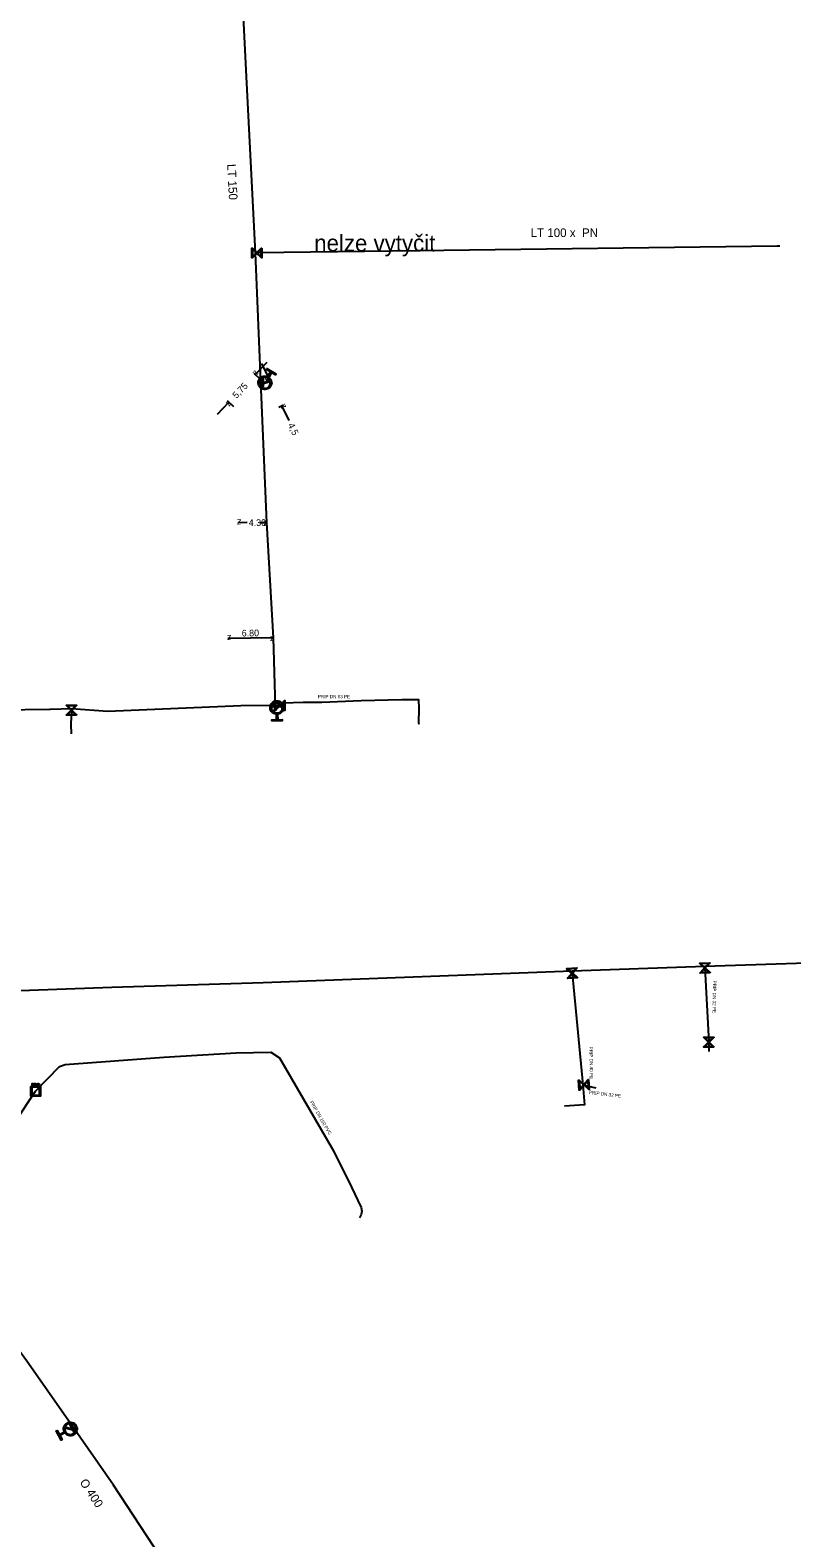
# Model space of a CAD drawing. Extents: x -643544 to -637295, y -1119190 to -1111715.
# Drawn here: x -641541.9 to -641427.5, y -1115022.6 to -1114796 of the extents above; entities that cross this region are included whole.
import ezdxf

# ---------------------------------------------------------------- set-up
doc = ezdxf.new("R2010")
doc.units = 0
for name, color, linetype in [('Default', 7, 'Continuous'), ('VP Hydrant', 7, 'Continuous'), ('VP Kótování', 7, 'Continuous'), ('VP Popis nerozlišený', 7, 'Continuous'), ('VP Popis přípojky', 7, 'Continuous'), ('VP Přípojka', 7, 'Continuous'), ('VP Řad', 7, 'Continuous'), ('VP Řad - popis', 7, 'Continuous'), ('VP Šachta', 7, 'Continuous'), ('VP Šoupě', 7, 'Continuous')]:
    doc.layers.add(name, color=color, linetype=linetype)

msp = doc.modelspace()

# ---------------------------------------------------------------- linework, layer by layer
at = {"layer": 'Default'}
for points in [[(-641506.09, -1114848.17), (-641505.8, -1114848.37), (-641505.7, -1114848.72), (-641505.59, -1114849.12), (-641505.8, -1114849.48), (-641506.01, -1114849.84), (-641506.4, -1114849.95), (-641506.8, -1114850.06), (-641507.16, -1114849.85), (-641507.52, -1114849.65), (-641507.63, -1114849.25), (-641507.74, -1114848.85), (-641507.54, -1114848.49), (-641507.33, -1114848.13), (-641506.93, -1114848.02), (-641506.58, -1114847.92), (-641506.25, -1114848.08)], [(-641505.91, -1114848.69), (-641506.01, -1114848.42), (-641506.26, -1114848.28), (-641506.56, -1114848.11), (-641506.88, -1114848.2), (-641507.21, -1114848.29), (-641507.37, -1114848.58), (-641507.52, -1114848.83), (-641507.47, -1114849.11)], [(-641507.42, -1114849.29), (-641507.32, -1114849.55), (-641507.07, -1114849.69), (-641506.78, -1114849.86), (-641506.45, -1114849.77), (-641506.13, -1114849.68), (-641505.96, -1114849.39), (-641505.82, -1114849.14), (-641505.86, -1114848.86)], [(-641504.94, -1114898.79), (-641505.3, -1114898.76), (-641505.56, -1114898.51), (-641505.85, -1114898.22), (-641505.86, -1114897.8), (-641505.86, -1114897.39), (-641505.58, -1114897.09), (-641505.29, -1114896.8), (-641504.87, -1114896.79), (-641504.46, -1114896.79), (-641504.16, -1114897.07), (-641503.86, -1114897.36), (-641503.86, -1114897.78), (-641503.85, -1114898.19), (-641504.14, -1114898.49), (-641504.4, -1114898.75), (-641504.75, -1114898.79)], [(-641504.36, -1114897.15), (-641504.58, -1114896.98), (-641504.87, -1114896.98), (-641505.2, -1114896.98), (-641505.44, -1114897.22), (-641505.67, -1114897.47), (-641505.67, -1114897.8), (-641505.67, -1114898.09), (-641505.49, -1114898.31)], [(-641505.36, -1114898.43), (-641505.14, -1114898.61), (-641504.85, -1114898.6), (-641504.51, -1114898.6), (-641504.27, -1114898.36), (-641504.04, -1114898.12), (-641504.04, -1114897.78), (-641504.05, -1114897.49), (-641504.23, -1114897.27)], [(-641541.5, -1114954.3), (-641541.46, -1114954.3), (-641541.44, -1114954.31), (-641541.42, -1114954.31), (-641541.4, -1114954.33), (-641541.38, -1114954.34), (-641541.37, -1114954.36), (-641541.36, -1114954.38), (-641541.36, -1114954.41), (-641541.36, -1114954.46), (-641541.39, -1114954.49), (-641541.42, -1114954.52), (-641541.49, -1114954.52)], [(-641541.49, -1114954.48), (-641541.45, -1114954.48), (-641541.43, -1114954.46), (-641541.41, -1114954.44), (-641541.41, -1114954.41), (-641541.41, -1114954.39), (-641541.42, -1114954.37), (-641541.43, -1114954.36), (-641541.45, -1114954.35), (-641541.46, -1114954.35), (-641541.5, -1114954.35)], [(-641541.11, -1114954.59), (-641541.13, -1114954.56), (-641541.14, -1114954.54), (-641541.15, -1114954.52), (-641541.16, -1114954.52), (-641541.17, -1114954.51), (-641541.19, -1114954.51), (-641541.19, -1114954.5), (-641541.21, -1114954.5)], [(-641541.17, -1114954.46), (-641541.13, -1114954.46), (-641541.11, -1114954.46), (-641541.1, -1114954.45), (-641541.09, -1114954.44), (-641541.08, -1114954.42), (-641541.08, -1114954.4), (-641541.08, -1114954.38), (-641541.1, -1114954.36), (-641541.11, -1114954.35), (-641541.15, -1114954.35)], [(-641541.16, -1114954.3), (-641541.11, -1114954.3), (-641541.08, -1114954.31), (-641541.06, -1114954.32), (-641541.04, -1114954.35), (-641541.03, -1114954.37), (-641541.03, -1114954.4), (-641541.03, -1114954.44), (-641541.05, -1114954.47), (-641541.08, -1114954.49), (-641541.13, -1114954.5), (-641541.11, -1114954.51), (-641541.1, -1114954.52), (-641541.08, -1114954.54), (-641541.06, -1114954.57)], [(-641540.7, -1114954.31), (-641540.66, -1114954.31), (-641540.64, -1114954.31), (-641540.62, -1114954.31), (-641540.6, -1114954.33), (-641540.58, -1114954.34), (-641540.57, -1114954.36), (-641540.56, -1114954.38), (-641540.56, -1114954.41), (-641540.56, -1114954.46), (-641540.59, -1114954.49), (-641540.62, -1114954.52), (-641540.69, -1114954.52)], [(-641540.69, -1114954.48), (-641540.65, -1114954.48), (-641540.63, -1114954.46), (-641540.61, -1114954.44), (-641540.61, -1114954.41), (-641540.61, -1114954.39), (-641540.62, -1114954.37), (-641540.63, -1114954.36), (-641540.65, -1114954.35), (-641540.66, -1114954.35), (-641540.69, -1114954.35)], [(-641536.82, -1115006.61), (-641536.97, -1115006.28), (-641536.87, -1115005.93), (-641536.76, -1115005.53), (-641536.4, -1115005.33), (-641536.04, -1115005.12), (-641535.64, -1115005.24), (-641535.24, -1115005.35), (-641535.04, -1115005.71), (-641534.84, -1115006.07), (-641534.95, -1115006.47), (-641535.06, -1115006.87), (-641535.42, -1115007.07), (-641535.78, -1115007.27), (-641536.18, -1115007.16), (-641536.53, -1115007.07), (-641536.73, -1115006.77)], [(-641535.11, -1115006.33), (-641535.06, -1115006.05), (-641535.2, -1115005.8), (-641535.37, -1115005.51), (-641535.69, -1115005.42), (-641536.02, -1115005.33), (-641536.31, -1115005.49), (-641536.56, -1115005.64), (-641536.66, -1115005.89)], [(-641536.71, -1115006.07), (-641536.76, -1115006.35), (-641536.62, -1115006.6), (-641536.45, -1115006.9), (-641536.13, -1115006.99), (-641535.81, -1115007.08), (-641535.51, -1115006.91), (-641535.26, -1115006.77), (-641535.15, -1115006.5)]]:
    msp.add_open_spline(points, degree=3, dxfattribs=at)
at = {"layer": 'VP Hydrant'}
for points in [[(-641506.25, -1114848.08), (-641505.84, -1114847.36), (-641506.44, -1114847.02), (-641506.35, -1114846.86), (-641505, -1114847.64), (-641505.09, -1114847.8), (-641505.69, -1114847.46), (-641506.09, -1114848.17)], [(-641507.47, -1114849.11), (-641505.91, -1114848.69)], [(-641505.86, -1114848.86), (-641507.42, -1114849.29)], [(-641504.75, -1114898.79), (-641504.74, -1114899.61), (-641504.05, -1114899.6), (-641504.05, -1114899.78), (-641505.61, -1114899.8), (-641505.62, -1114899.62), (-641504.93, -1114899.61), (-641504.94, -1114898.79)], [(-641505.49, -1114898.31), (-641504.36, -1114897.15)], [(-641504.23, -1114897.27), (-641505.36, -1114898.43)], [(-641536.73, -1115006.77), (-641537.45, -1115007.17), (-641537.11, -1115007.77), (-641537.27, -1115007.86), (-641538.04, -1115006.5), (-641537.88, -1115006.41), (-641537.54, -1115007.01), (-641536.82, -1115006.61)], [(-641535.15, -1115006.5), (-641536.71, -1115006.07)], [(-641536.66, -1115005.89), (-641535.11, -1115006.33)]]:
    msp.add_lwpolyline(points, dxfattribs=at)
at = {"layer": 'VP Kótování'}
for points in [[(-641506.37, -1114845.93), (-641508.1, -1114847.74)], [(-641507.17, -1114846.11), (-641506.08, -1114848.36)], [(-641507.35, -1114848.46), (-641508.28, -1114847.57)], [(-641506.54, -1114848.58), (-641505.85, -1114848.25)], [(-641513.8, -1114853.7), (-641512.07, -1114851.89)], [(-641511.32, -1114852.61), (-641512.26, -1114851.72)], [(-641504.57, -1114852.63), (-641503.89, -1114852.3)], [(-641503.02, -1114854.66), (-641504.11, -1114852.41)], [(-641509.34, -1114870), (-641510.71, -1114870.01)], [(-641507.37, -1114869.99), (-641506.41, -1114869.99)], [(-641505.4, -1114887.29), (-641512.21, -1114887.39)]]:
    msp.add_lwpolyline(points, dxfattribs=at)
at = {"layer": 'VP Přípojka'}
for points in [[(-641507.3, -1114848.81), (-641506.99, -1114848.8), (-641506.67, -1114848.99)], [(-641505.16, -1114897.47), (-641504.86, -1114897.47), (-641504.63, -1114897.47), (-641504.41, -1114897.47), (-641503.88, -1114897.06), (-641500.89, -1114896.96), (-641498.08, -1114896.97), (-641492.19, -1114896.75), (-641486.08, -1114896.59), (-641483.56, -1114896.57), (-641483.53, -1114897.97), (-641483.56, -1114900.02), (-641483.55, -1114900.27)], [(-641535.74, -1114897.97), (-641535.72, -1114898.18), (-641535.81, -1114900.26), (-641535.77, -1114901.76)], [(-641504.86, -1114897.79), (-641504.86, -1114897.63), (-641504.86, -1114897.47)], [(-641460.47, -1114937.36), (-641460.46, -1114937.71), (-641458.86, -1114954.5), (-641458.64, -1114957.51), (-641461.63, -1114957.71)], [(-641440.54, -1114936.64), (-641440.53, -1114936.92), (-641439.94, -1114948.06), (-641439.96, -1114949.45)], [(-641557.93, -1114975.27), (-641557.4, -1114974.76), (-641552.13, -1114970.67), (-641551.76, -1114969.69), (-641547.75, -1114964.65), (-641544.09, -1114959.88), (-641541.12, -1114955.45), (-641537.52, -1114951.73), (-641536.67, -1114951.41), (-641521.87, -1114950.34), (-641510.99, -1114949.66), (-641505.78, -1114949.55), (-641504.47, -1114950.43), (-641496.33, -1114964.41), (-641493.64, -1114969.85), (-641492.2, -1114972.91), (-641492.09, -1114973.46), (-641492.17, -1114973.97), (-641492.45, -1114974.48)], [(-641458.86, -1114954.5), (-641456.92, -1114954.92)], [(-641535.55, -1115005.87), (-641535.68, -1115005.98), (-641535.91, -1115006.2)]]:
    msp.add_lwpolyline(points, dxfattribs=at)
at = {"layer": 'VP Řad'}
for points in [[(-641510.78, -1114777), (-641509.44, -1114803.95), (-641508.11, -1114829.45)], [(-641429.26, -1114828.44), (-641429.69, -1114828.44), (-641483.64, -1114829.13), (-641507.86, -1114829.48), (-641508.11, -1114829.45)], [(-641508.11, -1114829.45), (-641507.3, -1114848.81), (-641506.41, -1114869.99), (-641505.4, -1114887.29), (-641505.18, -1114895.97), (-641505.17, -1114896.95), (-641505.16, -1114897.47)], [(-641505.16, -1114897.47), (-641505.75, -1114897.47), (-641510.28, -1114897.55), (-641530.27, -1114898.36), (-641535.74, -1114897.97), (-641538.9, -1114898.08), (-641539.03, -1114898.07), (-641561.17, -1114898.4), (-641561.28, -1114898.37)], [(-641560, -1114940.9), (-641529.66, -1114939.79), (-641506.9, -1114939.12), (-641460.47, -1114937.36), (-641440.54, -1114936.64), (-641416.03, -1114935.84), (-641401.22, -1114932.69)], [(-641510.23, -1115053.08), (-641508.66, -1115052.38), (-641509.2, -1115047.94), (-641511.62, -1115043.14), (-641520.33, -1115028.47), (-641529.42, -1115014.62), (-641535.55, -1115005.87), (-641542.45, -1114996.02), (-641549.75, -1114985.99), (-641554.32, -1114979.81), (-641557.93, -1114975.27), (-641563.9, -1114967.78), (-641568.95, -1114960.81), (-641569.03, -1114960.7)]]:
    msp.add_lwpolyline(points, dxfattribs=at)
at = {"layer": 'VP Šachta'}
for points in [[(-641540.41, -1114954.73), (-641540.41, -1114956.18), (-641541.83, -1114956.18), (-641541.83, -1114954.73), (-641540.41, -1114954.73)], [(-641541.71, -1114954.85), (-641541.71, -1114956.06), (-641540.53, -1114956.06), (-641540.53, -1114954.85), (-641541.71, -1114954.85)], [(-641541.63, -1114954.66), (-641541.63, -1114954.3), (-641541.5, -1114954.3)], [(-641541.49, -1114954.52), (-641541.59, -1114954.52), (-641541.59, -1114954.66), (-641541.63, -1114954.66)], [(-641541.5, -1114954.35), (-641541.59, -1114954.35), (-641541.59, -1114954.48)], [(-641541.59, -1114954.48), (-641541.49, -1114954.48)], [(-641541.31, -1114954.66), (-641541.31, -1114954.3), (-641541.16, -1114954.3)], [(-641541.21, -1114954.5), (-641541.27, -1114954.5), (-641541.27, -1114954.66), (-641541.31, -1114954.66)], [(-641541.15, -1114954.35), (-641541.27, -1114954.35), (-641541.27, -1114954.46)], [(-641541.27, -1114954.46), (-641541.17, -1114954.46)], [(-641541.06, -1114954.57), (-641541, -1114954.66), (-641541.06, -1114954.66), (-641541.11, -1114954.59)], [(-641540.95, -1114954.67), (-641540.95, -1114954.31), (-641540.9, -1114954.31), (-641540.9, -1114954.67), (-641540.95, -1114954.67)], [(-641540.83, -1114954.67), (-641540.83, -1114954.31), (-641540.7, -1114954.31)], [(-641540.69, -1114954.52), (-641540.79, -1114954.52), (-641540.79, -1114954.67), (-641540.83, -1114954.67)], [(-641540.69, -1114954.35), (-641540.79, -1114954.35), (-641540.79, -1114954.48)], [(-641540.79, -1114954.48), (-641540.69, -1114954.48)]]:
    msp.add_lwpolyline(points, dxfattribs=at)
at = {"layer": 'VP Šoupě'}
for points in [[(-641507.11, -1114828.73), (-641507.11, -1114830.23), (-641507.18, -1114830.23), (-641507.26, -1114830.13), (-641507.86, -1114829.54), (-641508.54, -1114830.23), (-641508.61, -1114830.23), (-641508.61, -1114828.73), (-641508.55, -1114828.73), (-641507.86, -1114829.42), (-641507.27, -1114828.82), (-641507.18, -1114828.73), (-641507.11, -1114828.73)], [(-641508.52, -1114830.08), (-641507.92, -1114829.48), (-641508.52, -1114828.89), (-641508.52, -1114830.08)], [(-641507.21, -1114828.89), (-641507.8, -1114829.48), (-641507.2, -1114830.07), (-641507.21, -1114828.89)], [(-641506.94, -1114848.05), (-641506.94, -1114849.55), (-641507.03, -1114849.55), (-641507.03, -1114848.05), (-641506.94, -1114848.05)], [(-641505.15, -1114898.22), (-641505.17, -1114896.72), (-641505.1, -1114896.72), (-641505.01, -1114896.82), (-641504.41, -1114897.4), (-641503.73, -1114896.71), (-641503.67, -1114896.71), (-641503.65, -1114898.21), (-641503.72, -1114898.21), (-641504.41, -1114897.53), (-641505, -1114898.13), (-641505.09, -1114898.22), (-641505.15, -1114898.22)], [(-641505.06, -1114898.07), (-641504.47, -1114897.47), (-641505.07, -1114896.88), (-641505.06, -1114898.07)], [(-641503.76, -1114896.86), (-641504.35, -1114897.47), (-641503.75, -1114898.06), (-641503.76, -1114896.86)], [(-641534.97, -1114898.92), (-641536.47, -1114898.93), (-641536.47, -1114898.87), (-641536.37, -1114898.78), (-641535.78, -1114898.18), (-641536.48, -1114897.5), (-641536.48, -1114897.43), (-641534.98, -1114897.42), (-641534.98, -1114897.48), (-641535.66, -1114898.18), (-641535.06, -1114898.76), (-641534.97, -1114898.85), (-641534.97, -1114898.92)], [(-641536.33, -1114897.52), (-641535.72, -1114898.11), (-641535.13, -1114897.51), (-641536.33, -1114897.52)], [(-641535.12, -1114898.83), (-641535.72, -1114898.24), (-641536.31, -1114898.84), (-641535.12, -1114898.83)], [(-641504.11, -1114897.67), (-641505.61, -1114897.69), (-641505.61, -1114897.6), (-641504.11, -1114897.58), (-641504.11, -1114897.67)], [(-641459.65, -1114938.4), (-641461.15, -1114938.52), (-641461.15, -1114938.45), (-641461.07, -1114938.35), (-641460.52, -1114937.72), (-641461.26, -1114937.09), (-641461.27, -1114937.02), (-641459.77, -1114936.9), (-641459.76, -1114936.97), (-641460.4, -1114937.71), (-641459.76, -1114938.25), (-641459.66, -1114938.33), (-641459.65, -1114938.4)], [(-641461.11, -1114937.1), (-641460.47, -1114937.65), (-641459.92, -1114937.01), (-641461.11, -1114937.1)], [(-641439.75, -1114937.64), (-641441.25, -1114937.7), (-641441.25, -1114937.63), (-641441.16, -1114937.54), (-641440.59, -1114936.92), (-641441.3, -1114936.26), (-641441.31, -1114936.2), (-641439.81, -1114936.14), (-641439.8, -1114936.21), (-641440.47, -1114936.92), (-641439.85, -1114937.49), (-641439.76, -1114937.58), (-641439.75, -1114937.64)], [(-641441.15, -1114936.29), (-641440.53, -1114936.86), (-641439.96, -1114936.24), (-641441.15, -1114936.29)], [(-641439.91, -1114937.55), (-641440.53, -1114936.98), (-641441.1, -1114937.6), (-641439.91, -1114937.55)], [(-641459.82, -1114938.32), (-641460.46, -1114937.77), (-641461, -1114938.41), (-641459.82, -1114938.32)], [(-641439.2, -1114948.82), (-641440.7, -1114948.8), (-641440.7, -1114948.74), (-641440.6, -1114948.65), (-641440, -1114948.06), (-641440.68, -1114947.37), (-641440.68, -1114947.3), (-641439.18, -1114947.32), (-641439.18, -1114947.38), (-641439.88, -1114948.06), (-641439.29, -1114948.66), (-641439.2, -1114948.75), (-641439.2, -1114948.82)], [(-641439.35, -1114948.72), (-641439.94, -1114948.12), (-641440.54, -1114948.71), (-641439.35, -1114948.72)], [(-641440.53, -1114947.4), (-641439.94, -1114948), (-641439.34, -1114947.41), (-641440.53, -1114947.4)], [(-641458.01, -1114953.69), (-641457.91, -1114955.19), (-641457.98, -1114955.19), (-641458.07, -1114955.1), (-641458.7, -1114954.55), (-641459.35, -1114955.28), (-641459.41, -1114955.28), (-641459.51, -1114953.78), (-641459.44, -1114953.78), (-641458.71, -1114954.42), (-641458.16, -1114953.79), (-641458.07, -1114953.69), (-641458.01, -1114953.69)], [(-641459.33, -1114955.12), (-641458.77, -1114954.49), (-641459.4, -1114953.93), (-641459.33, -1114955.12)], [(-641458.09, -1114953.85), (-641458.65, -1114954.48), (-641458.02, -1114955.03), (-641458.09, -1114953.85)], [(-641536.01, -1115005.3), (-641535.27, -1115006.61), (-641535.35, -1115006.66), (-641536.09, -1115005.35), (-641536.01, -1115005.3)]]:
    msp.add_lwpolyline(points, dxfattribs=at)

# ---------------------------------------------------------------- texts
at = {"layer": 'VP Kótování'}
for s, rotation, p in [('z', 226.3006, (-641508.12, -1114847.03)), ('5,75', 46.3006, (-641510.94, -1114851.43)), ('z', 295.9264, (-641506.75, -1114848.13)), ('z', 46.3006, (-641512.06, -1114852.6)), ('z', 115.9264, (-641503.44, -1114852.64)), ('4,5', 295.9264, (-641503.25, -1114855.33)), ('z', 180.2667, (-641510.21, -1114869.51)), ('4.30', 0.2667, (-641509.09, -1114870.5)), ('z', 0.2667, (-641506.91, -1114870.49)), ('z', 180.8589, (-641511.72, -1114886.88)), ('6.80', 0.8589, (-641510.14, -1114887.11)), ('z', 0.8589, (-641505.9, -1114887.8))]:
    msp.add_text(s, height=1, rotation=rotation, dxfattribs=at).set_placement(p)
at = {"layer": 'VP Popis nerozlišený'}
msp.add_text('nelze vytyčit', height=2.5, dxfattribs=at).set_placement((-641499.25, -1114829.24))
at = {"layer": 'VP Popis přípojky'}
for s, rotation, p in [('PRIP DN 63 PE', 359.8772, (-641498.72, -1114896.38)), ('PRIP DN 32 PE', 269.7697, (-641439.33, -1114938.83)), ('PRIP DN 40 PE', 270.7687, (-641457.89, -1114948.75)), ('PRIP DN 32 PE', 353.1818, (-641458, -1114955.84)), ('PRIP DN 160 PVC', 300.2106, (-641499.94, -1114957.06))]:
    msp.add_text(s, height=0.5, rotation=rotation, dxfattribs=at).set_placement(p)
at = {"layer": 'VP Řad - popis'}
for s, rotation, p in [('LT 150', 272.9885, (-641512.34, -1114816.13)), ('LT 100 x  PN ', 0.1071, (-641466.73, -1114827.09)), ('O 400', 303.2737, (-641534.56, -1115014.21))]:
    msp.add_text(s, height=1.3, rotation=rotation, dxfattribs=at).set_placement(p)

doc.saveas('drawing.dxf')
